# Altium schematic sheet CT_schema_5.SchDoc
size 370 x 243 mm
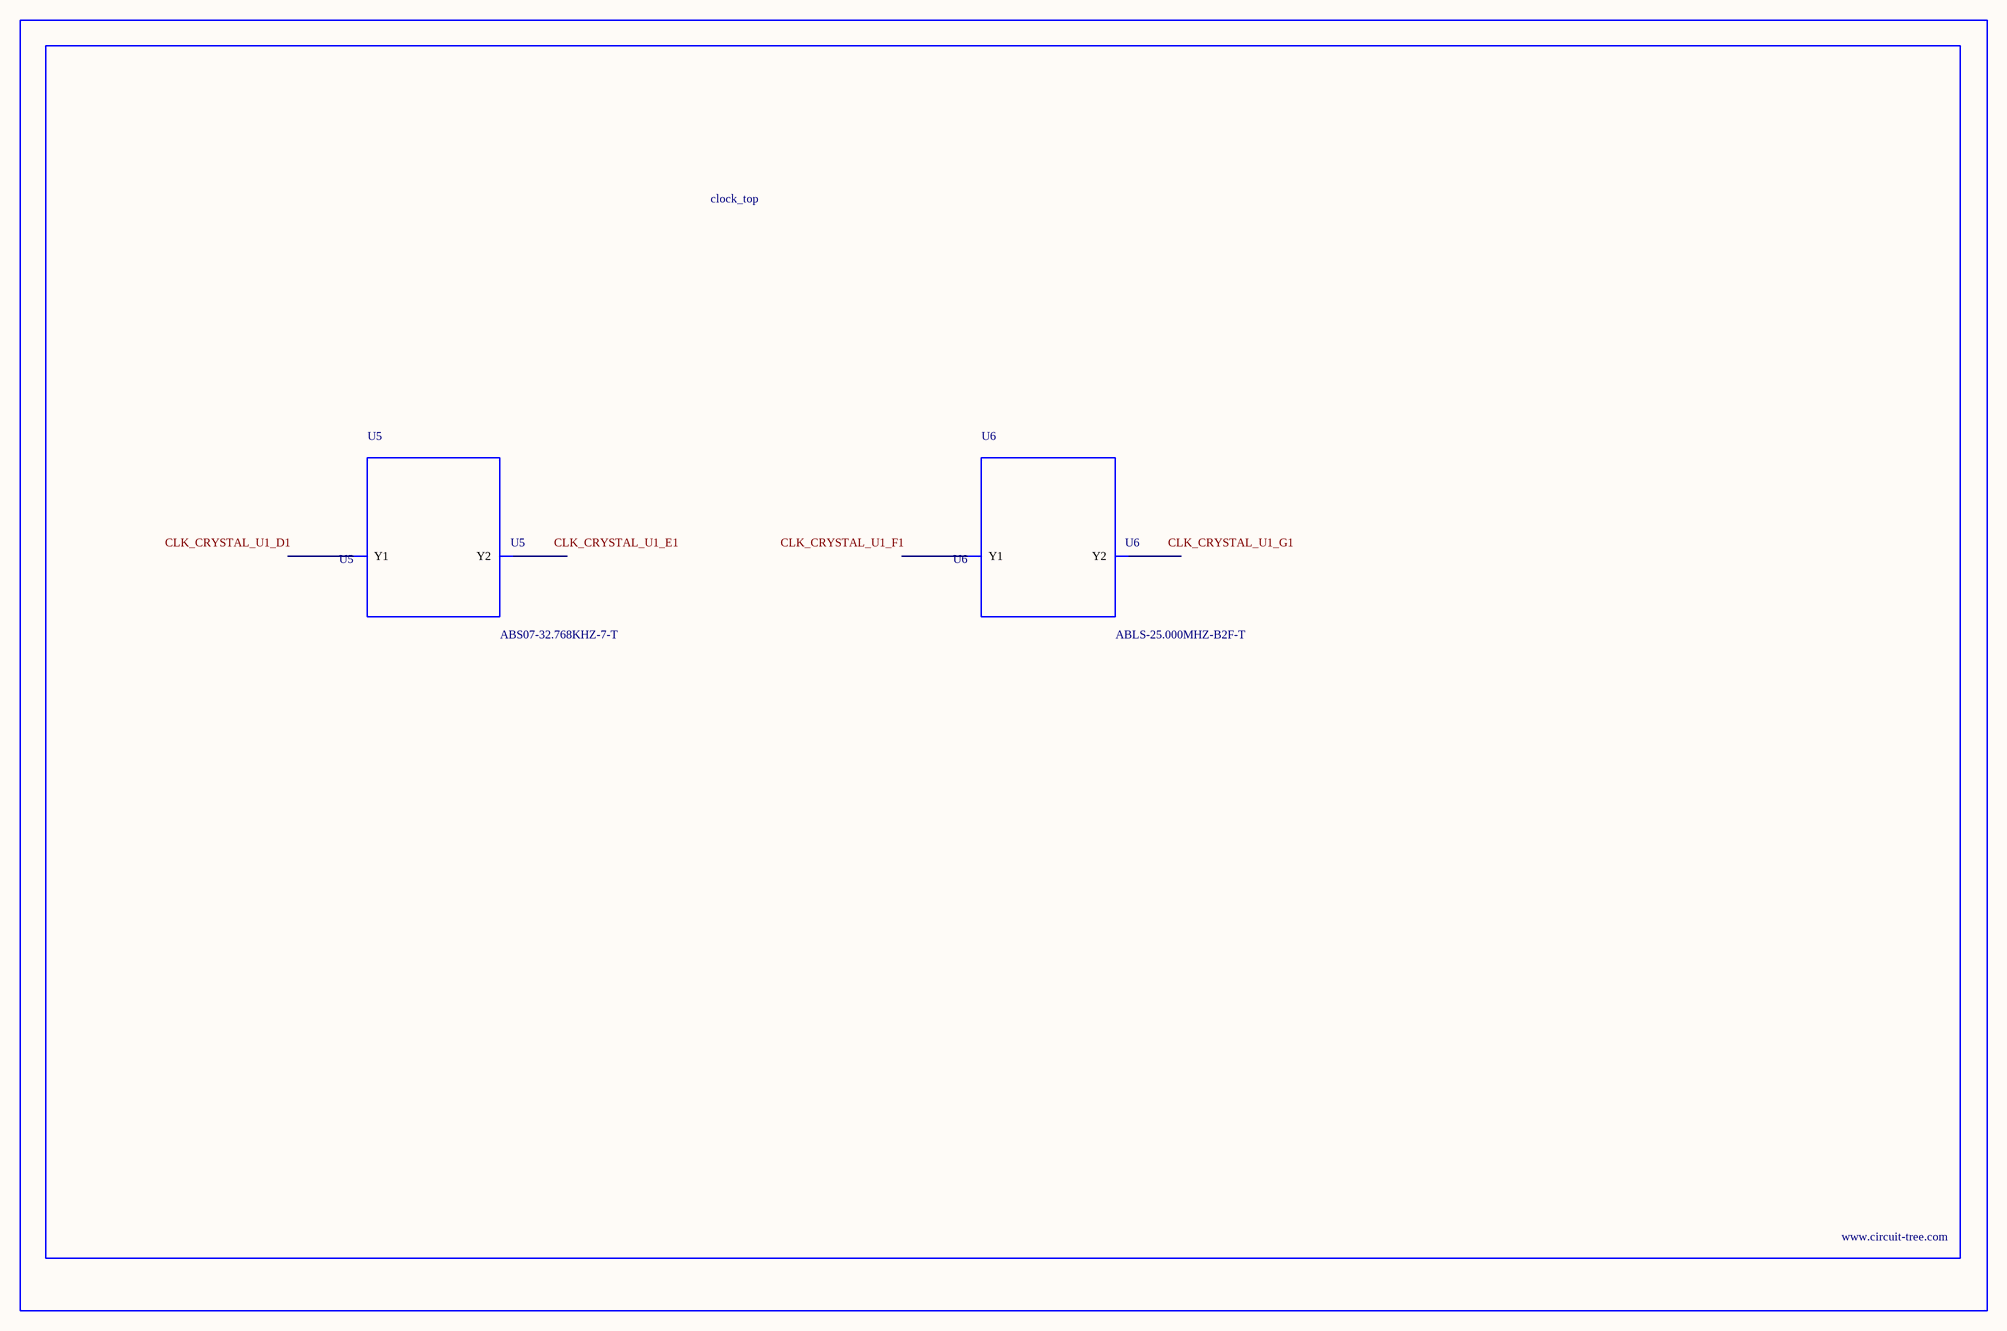
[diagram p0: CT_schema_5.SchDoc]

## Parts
BORDER4  (no value)
U5  ABS07-32.768KHZ-7-T  [ABS07-32.768KHZ-7-T]
U6  ABLS-25.000MHZ-B2F-T  [ABLS-25.000MHZ-B2F-T]

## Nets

Not connected (* = marked no-connect by the designer): U5 1(Y1) 2(Y2); U6 1(Y1) 2(Y2)

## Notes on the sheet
- Labels drawn without touching a wire or pin: CLK_CRYSTAL_U1_D1, CLK_CRYSTAL_U1_E1, CLK_CRYSTAL_U1_F1, CLK_CRYSTAL_U1_G1

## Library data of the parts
BORDER4 = BORDER_PAGE4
